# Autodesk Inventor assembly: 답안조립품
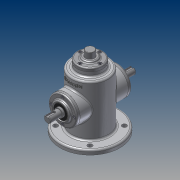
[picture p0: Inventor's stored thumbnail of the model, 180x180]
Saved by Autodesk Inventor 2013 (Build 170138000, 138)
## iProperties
Created: 2014-12
Part Number: 답안조립품
Document SubType Name: Assembly
Designer: CAD-B18
Author: CAD-B18
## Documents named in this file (12)
- C:\Users\CAD-B18\Desktop\441228V1010\답안조립품.iam
- C:\Users\CAD-B18\Desktop\441228V1010\본체.ipt
- C:\Users\CAD-B18\Desktop\441228V1010\베어링 6002.ipt
- 베어링 6002.ipt
- C:\Users\CAD-B18\Desktop\441228V1010\커버.ipt
- C:\Users\CAD-B18\Desktop\441228V1010\오일실.ipt
- 오일실.ipt
- C:\Users\CAD-B18\Desktop\441228V1010\상단커버.ipt
- C:\Users\CAD-B18\Desktop\441228V1010\슬라이드.ipt
- C:\Users\CAD-B18\Desktop\441228V1010\M3x0.5x8.ipt
- M3x0.5.ipt
- C:\Users\CAD-B18\Desktop\441228V1010\편심축.ipt
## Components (12 placed, 1 different names)
1. M3x0.5:9
2. M3x0.5:10
3. M3x0.5:11
4. M3x0.5:12
5. M3x0.5:2 — 각도:2
6. M3x0.5:3
7. M3x0.5:4
8. M3x0.5:5
9. M3x0.5:1 — 각도:3
10. M3x0.5:6
11. M3x0.5:7
12. M3x0.5:8
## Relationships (2: Angle 2)
- 각도:2 [Angle]: M3x0.5:2
- 각도:3 [Angle]: M3x0.5:1
